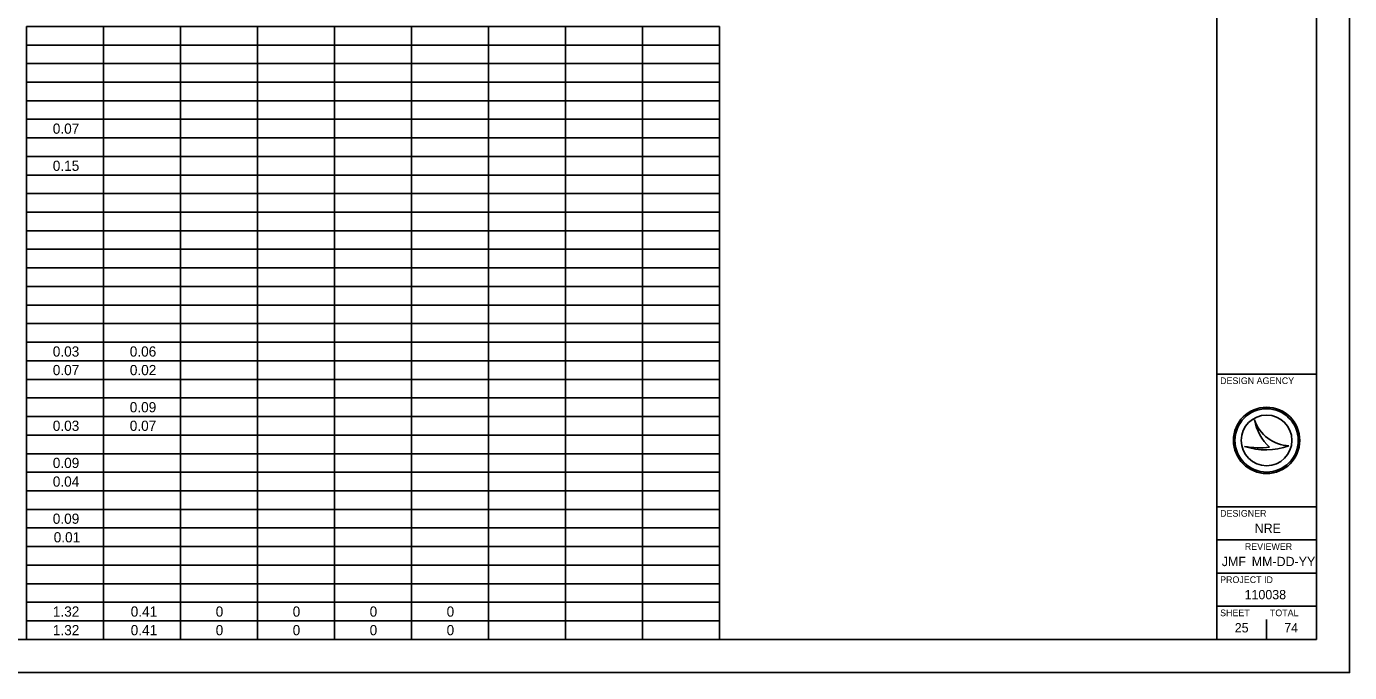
# Model space of a CAD drawing. Extents: x 0 to 34, y 0 to 22.
# Drawn here: x 14.06 to 34, y 0 to 9.74 of the extents above; entities that cross this region are included whole.
import ezdxf

# ---------------------------------------------------------------- set-up
doc = ezdxf.new("R2010")
doc.units = 0
for name, color, linetype in [('SH_Border', 7, 'Continuous'), ('SH_Cut_Line', 7, 'Continuous'), ('SH_Data', 7, 'Continuous'), ('SH_Text', 7, 'Continuous')]:
    doc.layers.add(name, color=color, linetype=linetype)

msp = doc.modelspace()

# ---------------------------------------------------------------- linework, layer by layer
at = {"layer": 'SH_Border'}
for p, q in [((32, 0.5), (32, 21.5)), ((32, 4.5), (33.5, 4.5)), ((32, 2.5), (33.5, 2.5)), ((32, 2), (33.5, 2)), ((32, 1.5), (33.5, 1.5)), ((32, 1), (33.5, 1))]:
    msp.add_line(p, q, dxfattribs=at)
msp.add_lwpolyline([(1.5, 21.5), (33.5, 21.5), (33.5, 0.5), (1.5, 0.5)], close=True, dxfattribs=at)
at = {"layer": 'SH_Cut_Line'}
msp.add_lwpolyline([(0, 0), (34, 0), (34, 22), (0, 22)], close=True, dxfattribs=at)
at = {"layer": 'SH_Data'}
for p, q in [((32.567, 3.81), (32.567, 3.81)), ((32.417, 3.41), (32.417, 3.41)), ((32.75, 3.5), (32.75, 3.5)), ((33.087, 3.419), (33.087, 3.419)), ((32.75, 0.5), (32.75, 0.8)), ((32.375, 0.675), (32.375, 0.675))]:
    msp.add_line(p, q, dxfattribs=at)
for radius in [0.5, 0.477, 0.477, 0.382]:
    msp.add_circle((32.75, 3.5), radius, dxfattribs=at)
for centre, radius, start, end in [((33.116, 3.998), 0.58, 198.9257, 198.9319), ((33.347, 3.97), 0.796, 191.6379, 191.6421), ((33.116, 3.998), 0.58, 198.9319, 267.1657), ((33.347, 3.97), 0.796, 191.6421, 226.0947), ((32.739, 4.37), 1.013, 251.4576, 290.0832), ((32.648, 4.654), 1.266, 259.4964, 259.4995), ((32.739, 4.37), 1.013, 251.4527, 251.4576), ((32.648, 4.654), 1.266, 259.4995, 276.6672)]:
    msp.add_arc(centre, radius, start, end, dxfattribs=at)
at = {"layer": 'SH_Text'}
for p, q in [((14.062, 9.741), (16.383, 9.741)), ((14.062, 9.741), (14.062, 9.181)), ((15.222, 9.741), (15.222, 9.181)), ((16.383, 9.741), (21.024, 9.741)), ((16.383, 9.741), (16.383, 9.181)), ((17.543, 9.741), (17.543, 9.181)), ((18.703, 9.741), (18.703, 9.181)), ((19.863, 9.741), (19.863, 9.181)), ((21.024, 9.741), (23.344, 9.741)), ((21.024, 9.741), (21.024, 9.181)), ((22.184, 9.741), (22.184, 9.181)), ((23.344, 9.741), (24.504, 9.741)), ((23.344, 9.741), (23.344, 9.181)), ((24.504, 9.741), (24.504, 9.181)), ((14.062, 9.461), (16.383, 9.461)), ((16.383, 9.461), (21.024, 9.461)), ((21.024, 9.461), (23.344, 9.461)), ((23.344, 9.461), (24.504, 9.461)), ((14.062, 9.181), (16.383, 9.181)), ((14.062, 9.181), (14.062, 8.341)), ((15.222, 9.181), (15.222, 8.341)), ((16.383, 9.181), (21.024, 9.181)), ((16.383, 9.181), (16.383, 8.341)), ((17.543, 9.181), (17.543, 8.341)), ((18.703, 9.181), (18.703, 8.341)), ((19.863, 9.181), (19.863, 8.341)), ((21.024, 9.181), (23.344, 9.181)), ((21.024, 9.181), (21.024, 8.341)), ((22.184, 9.181), (22.184, 8.341)), ((23.344, 9.181), (24.504, 9.181)), ((23.344, 9.181), (23.344, 8.341)), ((24.504, 9.181), (24.504, 8.341)), ((14.062, 8.901), (16.383, 8.901)), ((16.383, 8.901), (21.024, 8.901)), ((21.024, 8.901), (23.344, 8.901)), ((23.344, 8.901), (24.504, 8.901)), ((14.062, 8.621), (16.383, 8.621)), ((16.383, 8.621), (21.024, 8.621)), ((21.024, 8.621), (23.344, 8.621)), ((23.344, 8.621), (24.504, 8.621)), ((14.062, 8.341), (16.383, 8.341)), ((14.062, 8.341), (14.062, 7.781)), ((15.222, 8.341), (15.222, 7.781)), ((16.383, 8.341), (21.024, 8.341)), ((16.383, 8.341), (16.383, 7.781)), ((17.543, 8.341), (17.543, 7.781)), ((18.703, 8.341), (18.703, 7.781)), ((19.863, 8.341), (19.863, 7.781)), ((21.024, 8.341), (23.344, 8.341)), ((21.024, 8.341), (21.024, 7.781)), ((22.184, 8.341), (22.184, 7.781)), ((23.344, 8.341), (24.504, 8.341)), ((23.344, 8.341), (23.344, 7.781)), ((24.504, 8.341), (24.504, 7.781)), ((14.062, 8.061), (16.383, 8.061)), ((16.383, 8.061), (21.024, 8.061)), ((21.024, 8.061), (23.344, 8.061)), ((23.344, 8.061), (24.504, 8.061)), ((14.062, 7.781), (16.383, 7.781)), ((14.062, 7.781), (14.062, 6.941)), ((15.222, 7.781), (15.222, 6.941)), ((16.383, 7.781), (21.024, 7.781)), ((16.383, 7.781), (16.383, 6.941)), ((17.543, 7.781), (17.543, 6.941)), ((18.703, 7.781), (18.703, 6.941)), ((19.863, 7.781), (19.863, 6.941)), ((21.024, 7.781), (23.344, 7.781)), ((21.024, 7.781), (21.024, 6.941)), ((22.184, 7.781), (22.184, 6.941)), ((23.344, 7.781), (24.504, 7.781)), ((23.344, 7.781), (23.344, 6.941)), ((24.504, 7.781), (24.504, 6.941)), ((14.062, 7.501), (16.383, 7.501)), ((16.383, 7.501), (21.024, 7.501)), ((21.024, 7.501), (23.344, 7.501)), ((23.344, 7.501), (24.504, 7.501)), ((14.062, 7.221), (16.383, 7.221)), ((16.383, 7.221), (21.024, 7.221)), ((21.024, 7.221), (23.344, 7.221)), ((23.344, 7.221), (24.504, 7.221)), ((14.062, 6.941), (16.383, 6.941)), ((14.062, 6.941), (14.062, 6.381)), ((15.222, 6.941), (15.222, 6.381)), ((16.383, 6.941), (21.024, 6.941)), ((16.383, 6.941), (16.383, 6.381)), ((17.543, 6.941), (17.543, 6.381)), ((18.703, 6.941), (18.703, 6.381)), ((19.863, 6.941), (19.863, 6.381)), ((21.024, 6.941), (23.344, 6.941)), ((21.024, 6.941), (21.024, 6.381)), ((22.184, 6.941), (22.184, 6.381)), ((23.344, 6.941), (24.504, 6.941)), ((23.344, 6.941), (23.344, 6.381)), ((24.504, 6.941), (24.504, 6.381)), ((14.062, 6.661), (16.383, 6.661)), ((16.383, 6.661), (21.024, 6.661)), ((21.024, 6.661), (23.344, 6.661)), ((23.344, 6.661), (24.504, 6.661)), ((14.062, 6.381), (16.383, 6.381)), ((14.062, 6.381), (14.062, 0.5)), ((15.222, 6.381), (15.222, 0.5)), ((16.383, 6.381), (21.024, 6.381)), ((16.383, 6.381), (16.383, 0.5)), ((17.543, 6.381), (17.543, 0.5)), ((18.703, 6.381), (18.703, 0.5)), ((19.863, 6.381), (19.863, 0.5)), ((21.024, 6.381), (23.344, 6.381)), ((21.024, 6.381), (21.024, 0.5)), ((22.184, 6.381), (22.184, 0.5)), ((23.344, 6.381), (24.504, 6.381)), ((23.344, 6.381), (23.344, 0.5)), ((24.504, 6.381), (24.504, 0.5)), ((14.062, 6.101), (16.383, 6.101)), ((16.383, 6.101), (21.024, 6.101)), ((21.024, 6.101), (23.344, 6.101)), ((23.344, 6.101), (24.504, 6.101)), ((14.062, 5.821), (16.383, 5.821)), ((16.383, 5.821), (21.024, 5.821)), ((21.024, 5.821), (23.344, 5.821)), ((23.344, 5.821), (24.504, 5.821)), ((14.062, 5.541), (16.383, 5.541)), ((16.383, 5.541), (21.024, 5.541)), ((21.024, 5.541), (23.344, 5.541)), ((23.344, 5.541), (24.504, 5.541)), ((14.062, 5.261), (16.383, 5.261)), ((16.383, 5.261), (21.024, 5.261)), ((21.024, 5.261), (23.344, 5.261)), ((23.344, 5.261), (24.504, 5.261)), ((14.062, 4.981), (16.383, 4.981)), ((16.383, 4.981), (21.024, 4.981)), ((21.024, 4.981), (23.344, 4.981)), ((23.344, 4.981), (24.504, 4.981)), ((14.062, 4.7), (16.383, 4.7)), ((16.383, 4.7), (21.024, 4.7)), ((21.024, 4.7), (23.344, 4.7)), ((23.344, 4.7), (24.504, 4.7)), ((14.062, 4.42), (16.383, 4.42)), ((16.383, 4.42), (21.024, 4.42)), ((21.024, 4.42), (23.344, 4.42)), ((23.344, 4.42), (24.504, 4.42)), ((14.062, 4.14), (16.383, 4.14)), ((16.383, 4.14), (21.024, 4.14)), ((21.024, 4.14), (23.344, 4.14)), ((23.344, 4.14), (24.504, 4.14)), ((14.062, 3.86), (16.383, 3.86)), ((16.383, 3.86), (21.024, 3.86)), ((21.024, 3.86), (23.344, 3.86)), ((23.344, 3.86), (24.504, 3.86)), ((14.062, 3.58), (16.383, 3.58)), ((16.383, 3.58), (21.024, 3.58)), ((21.024, 3.58), (23.344, 3.58)), ((23.344, 3.58), (24.504, 3.58)), ((14.062, 3.3), (16.383, 3.3)), ((16.383, 3.3), (21.024, 3.3)), ((21.024, 3.3), (23.344, 3.3)), ((23.344, 3.3), (24.504, 3.3)), ((14.062, 3.02), (16.383, 3.02)), ((16.383, 3.02), (21.024, 3.02)), ((21.024, 3.02), (23.344, 3.02)), ((23.344, 3.02), (24.504, 3.02)), ((14.062, 2.74), (16.383, 2.74)), ((16.383, 2.74), (21.024, 2.74)), ((21.024, 2.74), (23.344, 2.74)), ((23.344, 2.74), (24.504, 2.74)), ((14.062, 2.46), (16.383, 2.46)), ((16.383, 2.46), (21.024, 2.46)), ((21.024, 2.46), (23.344, 2.46)), ((23.344, 2.46), (24.504, 2.46)), ((14.062, 2.18), (16.383, 2.18)), ((16.383, 2.18), (21.024, 2.18)), ((21.024, 2.18), (23.344, 2.18)), ((23.344, 2.18), (24.504, 2.18)), ((14.062, 1.9), (16.383, 1.9)), ((16.383, 1.9), (21.024, 1.9)), ((21.024, 1.9), (23.344, 1.9)), ((23.344, 1.9), (24.504, 1.9)), ((14.062, 1.62), (16.383, 1.62)), ((16.383, 1.62), (21.024, 1.62)), ((21.024, 1.62), (23.344, 1.62)), ((23.344, 1.62), (24.504, 1.62)), ((14.062, 1.34), (16.383, 1.34)), ((16.383, 1.34), (21.024, 1.34)), ((21.024, 1.34), (23.344, 1.34)), ((23.344, 1.34), (24.504, 1.34)), ((14.062, 1.06), (16.383, 1.06)), ((16.383, 1.06), (21.024, 1.06)), ((21.024, 1.06), (23.344, 1.06)), ((23.344, 1.06), (24.504, 1.06)), ((14.062, 0.78), (16.383, 0.78)), ((16.383, 0.78), (21.024, 0.78)), ((21.024, 0.78), (23.344, 0.78)), ((23.344, 0.78), (24.504, 0.78)), ((14.062, 0.5), (16.383, 0.5)), ((16.383, 0.5), (21.024, 0.5)), ((21.024, 0.5), (23.344, 0.5)), ((23.344, 0.5), (24.504, 0.5))]:
    msp.add_line(p, q, dxfattribs=at)

# ---------------------------------------------------------------- texts
at = {"layer": 'SH_Data'}
for s, height, p in [('DESIGN AGENCY', 0.1, (32.05, 4.35)), ('DESIGNER', 0.1, (32.05, 2.35)), ('NRE', 0.14, (32.571, 2.105)), ('REVIEWER', 0.1, (32.422, 1.85)), ('JMF', 0.14, (32.075, 1.605)), ('MM-DD-YY', 0.14, (32.527, 1.605)), ('PROJECT ID', 0.1, (32.05, 1.35)), ('110038', 0.14, (32.419, 1.105)), ('SHEET', 0.1, (32.05, 0.85)), ('TOTAL', 0.1, (32.8, 0.85)), ('25', 0.14, (32.27, 0.605)), ('74', 0.14, (33.016, 0.605))]:
    msp.add_text(s, height=height, dxfattribs=at).set_placement(p)
at = {"layer": 'SH_Text'}
for s, height, p in [('0.07', 0.1534, (14.459, 8.124)), ('0.15', 0.1534, (14.459, 7.564)), ('0.03', 0.1534, (14.459, 4.764)), ('0.06', 0.1534, (15.619, 4.764)), ('0.07', 0.1534, (14.459, 4.484)), ('0.02', 0.1534, (15.62, 4.484)), ('0.09', 0.1534, (15.619, 3.924)), ('0.03', 0.1534, (14.459, 3.644)), ('0.07', 0.1534, (15.619, 3.644)), ('0.09', 0.1534, (14.459, 3.084)), ('0.04', 0.1534, (14.459, 2.803)), ('0.09', 0.1534, (14.459, 2.243)), ('0.01', 0.1534, (14.473, 1.963)), ('1.32', 0.1534, (14.46, 0.843)), ('0.41', 0.1534, (15.633, 0.843)), ('0', 0.153, (16.914, 0.843)), ('0', 0.153, (18.074, 0.843)), ('0', 0.153, (19.234, 0.843)), ('0', 0.153, (20.394, 0.843)), ('1.32', 0.1534, (14.46, 0.563)), ('0.41', 0.1534, (15.633, 0.563)), ('0', 0.153, (16.914, 0.563)), ('0', 0.153, (18.074, 0.563)), ('0', 0.153, (19.234, 0.563)), ('0', 0.153, (20.394, 0.563))]:
    msp.add_text(s, height=height, dxfattribs=at).set_placement(p)

doc.saveas('drawing.dxf')
